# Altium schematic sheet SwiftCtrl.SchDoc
size 292 x 193 mm; Author: Power Lin; DocumentNumber: 1; SheetNumber: 1; SheetTotal: 4; Website: wiki-power.com
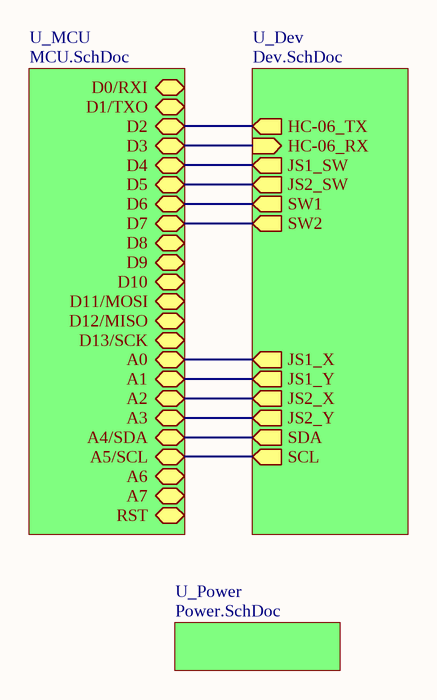
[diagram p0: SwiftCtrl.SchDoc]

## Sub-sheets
U_Dev = Dev.SchDoc: JS1_SW (out), JS1_Y (out), JS1_X (out), JS2_SW (out), JS2_Y (out), JS2_X (out), SDA (out), SCL (out), HC-06_TX (out), HC-06_RX (in), SW1 (out), SW2 (out)
U_MCU = MCU.SchDoc: D2 (bidir), D3 (bidir), D4 (bidir), D5 (bidir), D6 (bidir), D7 (bidir), A6 (bidir), A7 (bidir), D8 (bidir), D9 (bidir), D12/MISO (bidir), D10 (bidir), D11/MOSI (bidir), A0 (bidir), A1 (bidir), A4/SDA (bidir), A5/SCL (bidir), A2 (bidir), A3 (bidir), D13/SCK (bidir), RST (bidir), D0/RXI (bidir), D1/TXO (bidir)
U_Power = Power.SchDoc: no entries

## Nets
(unnamed): sheet U_Dev/JS1_SW, sheet U_MCU/D4
(unnamed): sheet U_Dev/JS1_Y, sheet U_MCU/A1  [a separate net that carries the same name]
(unnamed): sheet U_Dev/JS1_X, sheet U_MCU/A0  [a separate net that carries the same name]
(unnamed): sheet U_Dev/JS2_SW, sheet U_MCU/D5  [a separate net that carries the same name]
(unnamed): sheet U_Dev/JS2_Y, sheet U_MCU/A3  [a separate net that carries the same name]
(unnamed): sheet U_Dev/JS2_X, sheet U_MCU/A2  [a separate net that carries the same name]
(unnamed): sheet U_Dev/SDA, sheet U_MCU/A4/SDA  [a separate net that carries the same name]
(unnamed): sheet U_Dev/SCL, sheet U_MCU/A5/SCL  [a separate net that carries the same name]
(unnamed): sheet U_Dev/HC-06_TX, sheet U_MCU/D2  [a separate net that carries the same name]
(unnamed): sheet U_Dev/HC-06_RX, sheet U_MCU/D3  [a separate net that carries the same name]
(unnamed): sheet U_Dev/SW1, sheet U_MCU/D6  [a separate net that carries the same name]
(unnamed): sheet U_Dev/SW2, sheet U_MCU/D7  [a separate net that carries the same name]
